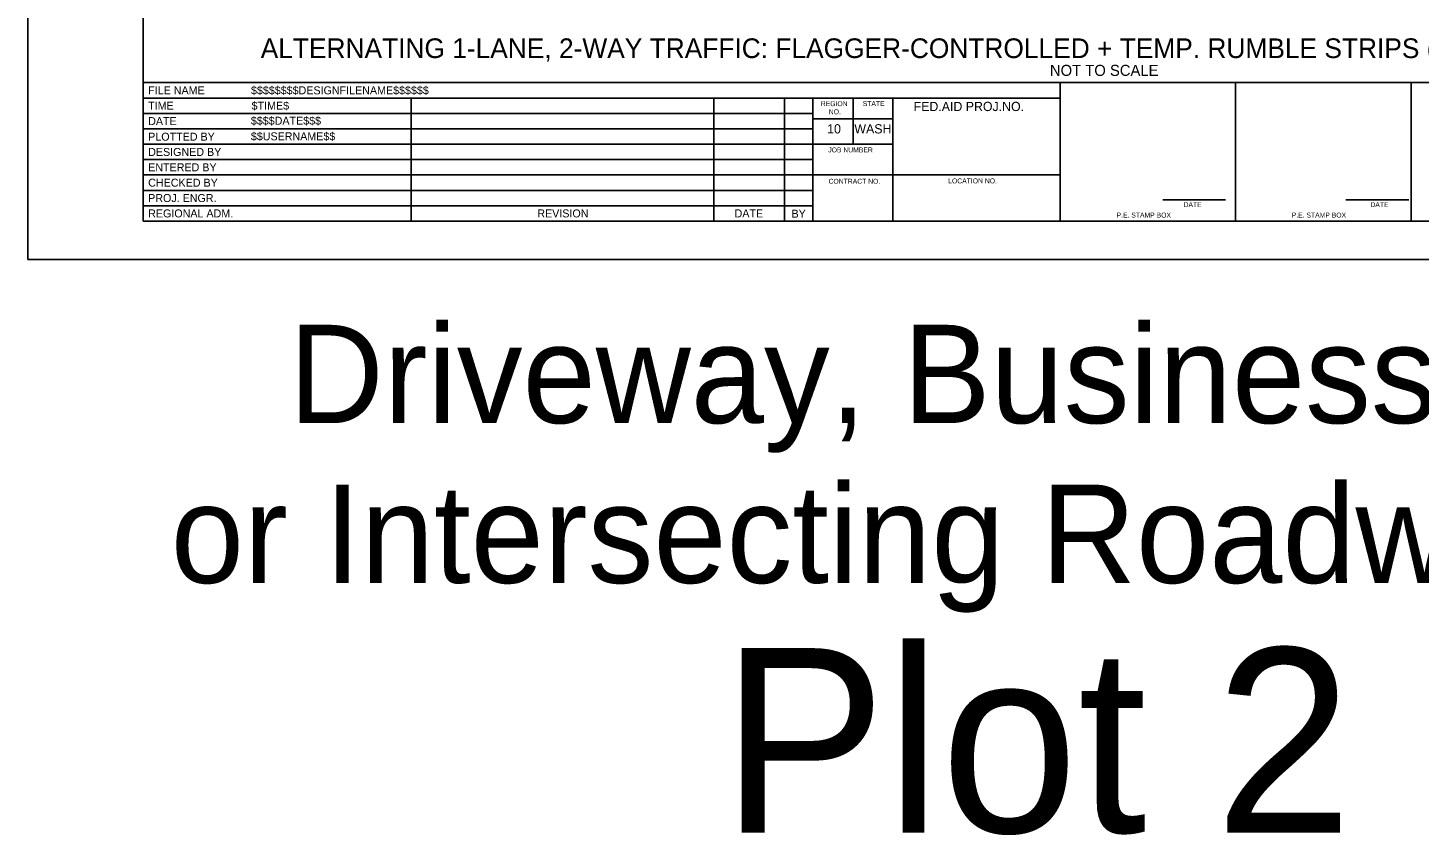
# Model space of a CAD drawing. Extents: x 99999.1 to 100095.7, y 99995 to 100010.7.
# Drawn here: x 100019.06 to 100030.38, y 99995.01 to 100001.57 of the extents above; entities that cross this region are included whole.
import ezdxf

# ---------------------------------------------------------------- set-up
doc = ezdxf.new("R2010")
doc.units = 0
for name, color, linetype in [('SH_DE_DetailHeading1Text', 7, 'Continuous'), ('SH_GI_PlotLimits', 7, 'Continuous'), ('SH_GI_SheetBorder', 7, 'Continuous'), ('SH_GI_SheetLocationText', 7, 'Continuous'), ('SH_GI_SheetTextInCells', 7, 'Continuous'), ('SH_GI_TitleBlockText', 7, 'Continuous')]:
    doc.layers.add(name, color=color, linetype=linetype)

msp = doc.modelspace()

# ---------------------------------------------------------------- linework, layer by layer
at = {"layer": 'SH_GI_PlotLimits'}
msp.add_lwpolyline([(100019.062, 99999.687), (100036.062, 99999.687), (100036.062, 100010.687), (100019.062, 100010.687)], close=True, dxfattribs=at)
at = {"layer": 'SH_GI_SheetBorder'}
for p, q in [((100020, 100010.375), (100020, 100000)), ((100020, 100001.126), (100035.75, 100001.126)), ((100027.457, 100000), (100027.457, 100001.126)), ((100028.883, 100000), (100028.883, 100001.126)), ((100030.309, 100001.126), (100030.309, 100000)), ((100020, 100001.001), (100027.457, 100001.001)), ((100022.179, 100001.001), (100022.179, 100000)), ((100024.641, 100001.001), (100024.641, 100000)), ((100025.216, 100001.001), (100025.216, 100000)), ((100025.445, 100001.001), (100025.445, 100000)), ((100025.772, 100000.625), (100025.772, 100001.001)), ((100026.096, 100000), (100026.096, 100001.001)), ((100020, 100000.876), (100022.182, 100000.876)), ((100022.182, 100000.876), (100025.447, 100000.876)), ((100026.096, 100000.831), (100025.447, 100000.831)), ((100020, 100000.751), (100022.182, 100000.751)), ((100022.182, 100000.751), (100025.447, 100000.751)), ((100020, 100000.625), (100025.447, 100000.625)), ((100026.096, 100000.625), (100025.447, 100000.625)), ((100020, 100000.5), (100025.447, 100000.5)), ((100020, 100000.375), (100025.447, 100000.375)), ((100027.457, 100000.375), (100025.447, 100000.375)), ((100020, 100000.25), (100025.447, 100000.25)), ((100020, 100000.125), (100025.447, 100000.125)), ((100028.29, 100000.173), (100028.802, 100000.173)), ((100029.78, 100000.173), (100030.291, 100000.173)), ((100020, 100000), (100035.75, 100000))]:
    msp.add_line(p, q, dxfattribs=at)

# ---------------------------------------------------------------- texts
at = {"layer": 'SH_DE_DetailHeading1Text'}
for s, height, p in [('ALTERNATING 1-LANE, 2-WAY TRAFFIC: FLAGGER-CONTROLLED + TEMP. RUMBLE STRIPS (HIGHWAYS, 40 MPH OR LESS)', 0.16, (100020.956, 100001.326)), ('NOT TO SCALE', 0.09, (100027.373, 100001.181))]:
    msp.add_text(s, height=height, rotation=360, dxfattribs=at).set_placement(p)
at = {"layer": 'SH_GI_SheetLocationText'}
for s, height, p in [('Driveway, Business Access,', 0.8, (100021.184, 99998.357)), ('or Intersecting Roadway Details', 0.8, (100020.225, 99997.057)), ('Plot 2', 1.5, (100024.702, 99995.027))]:
    msp.add_text(s, height=height, dxfattribs=at).set_placement(p)
at = {"layer": 'SH_GI_SheetTextInCells'}
for s, height, p in [('FILE NAME', 0.0651, (100020.041, 100001.031)), ('TIME', 0.0651, (100020.041, 100000.906)), ('REGION', 0.04, (100025.51, 100000.935)), ('NO.', 0.04, (100025.575, 100000.869)), ('STATE', 0.04, (100025.851, 100000.936)), ('FED.AID PROJ.NO.', 0.07506, (100026.265, 100000.895)), ('DATE', 0.0651, (100020.041, 100000.781)), ('10', 0.0751, (100025.562, 100000.713)), ('WASH', 0.0751, (100025.783, 100000.713)), ('PLOTTED BY', 0.0651, (100020.041, 100000.654)), ('DESIGNED BY', 0.06505, (100020.041, 100000.53)), ('JOB NUMBER', 0.04, (100025.571, 100000.559)), ('ENTERED BY', 0.0651, (100020.041, 100000.405)), ('CHECKED BY', 0.0651, (100020.041, 100000.28)), ('CONTRACT NO.', 0.04003, (100025.573, 100000.304)), ('LOCATION NO.', 0.04003, (100026.546, 100000.307)), ('PROJ. ENGR.', 0.06505, (100020.041, 100000.155)), ('REGIONAL ADM.', 0.06505, (100020.041, 100000.03)), ('REVISION', 0.0651, (100023.205, 100000.03)), ('DATE', 0.04, (100028.46, 100000.114)), ('DATE', 0.04, (100029.979, 100000.114)), ('DATE', 0.0651, (100024.809, 100000.03)), ('BY', 0.0651, (100025.272, 100000.028)), ('P.E. STAMP BOX', 0.04003, (100027.915, 100000.029)), ('P.E. STAMP BOX', 0.04003, (100029.339, 100000.029))]:
    msp.add_text(s, height=height, dxfattribs=at).set_placement(p)
at = {"layer": 'SH_GI_TitleBlockText'}
for s, height, p in [('$$$$$$$$DESIGNFILENAME$$$$$$', 0.06505, (100020.877, 100001.031)), ('$TIME$', 0.0651, (100020.882, 100000.906)), ('$$$$DATE$$$', 0.06505, (100020.876, 100000.784)), ('$$USERNAME$$', 0.06505, (100020.876, 100000.657))]:
    msp.add_text(s, height=height, dxfattribs=at).set_placement(p)

doc.saveas('drawing.dxf')
